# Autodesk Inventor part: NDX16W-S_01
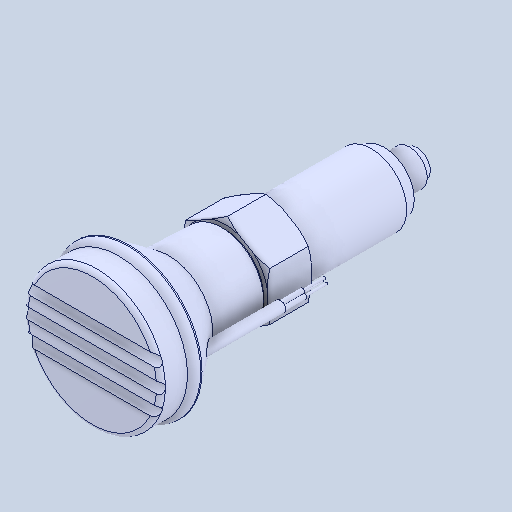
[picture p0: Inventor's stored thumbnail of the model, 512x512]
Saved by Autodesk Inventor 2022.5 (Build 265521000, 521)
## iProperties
Created: 2024-05
Part Number: NDX16W-S_01
Material: 一般
Document SubType Name: Modeling
Designer: ImaoCorp
Density: 1 g/cm^3
Appearance: 既定
Author: ImaoCorp
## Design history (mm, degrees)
feature "NDX16W-S_01"
node "ソリッド1"
